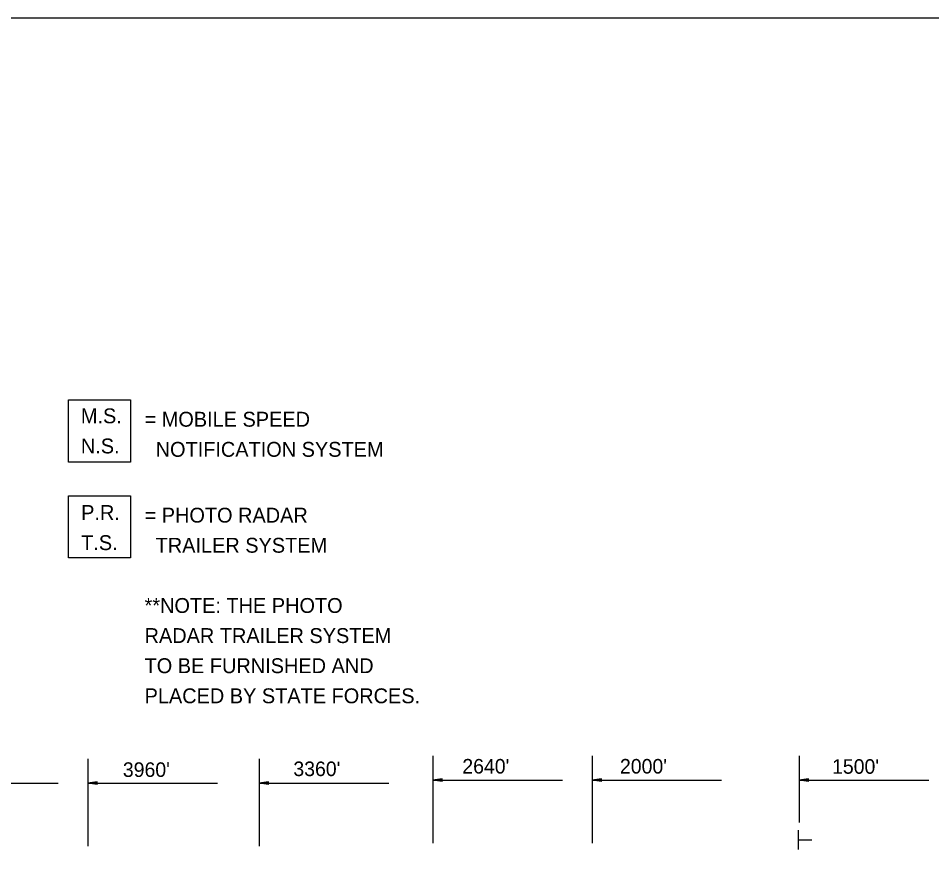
# Model space of a CAD drawing. Extents: x -100 to 745, y -1581 to -107.
# Drawn here: x 610.84 to 647.64, y -300.37 to -266.79 of the extents above; entities that cross this region are included whole.
import ezdxf

# ---------------------------------------------------------------- set-up
doc = ezdxf.new("R2010")
doc.units = 0
doc.layers.add('Default', color=7, linetype='Continuous')
doc.layers.add('R_Proposed Road', color=7, linetype='Continuous')

msp = doc.modelspace()

# ---------------------------------------------------------------- linework, layer by layer
at = {"layer": 'Default'}
for p, q in [((613.642, -296.624), (613.642, -300.145)), ((620.542, -296.624), (620.542, -300.145)), ((627.539, -296.504), (627.539, -300.025)), ((633.955, -296.504), (633.955, -300.025)), ((642.307, -296.504), (642.307, -299.189)), ((607.226, -297.603), (612.445, -297.603)), ((614.017, -297.547), (613.642, -297.603)), ((613.642, -297.603), (618.861, -297.603)), ((614.017, -297.659), (613.642, -297.603)), ((614.017, -297.556), (613.704, -297.603)), ((614.017, -297.65), (613.704, -297.603)), ((614.017, -297.566), (613.769, -297.603)), ((614.017, -297.64), (613.769, -297.603)), ((614.017, -297.575), (613.831, -297.603)), ((614.017, -297.631), (613.831, -297.603)), ((614.017, -297.584), (613.895, -297.603)), ((614.017, -297.621), (613.895, -297.603)), ((614.017, -297.594), (613.957, -297.603)), ((614.017, -297.612), (613.957, -297.603)), ((614.017, -297.659), (614.017, -297.547)), ((620.917, -297.547), (620.542, -297.603)), ((620.542, -297.603), (625.761, -297.603)), ((620.917, -297.659), (620.542, -297.603)), ((620.917, -297.556), (620.605, -297.603)), ((620.917, -297.65), (620.605, -297.603)), ((620.917, -297.566), (620.669, -297.603)), ((620.917, -297.64), (620.669, -297.603)), ((620.917, -297.575), (620.732, -297.603)), ((620.917, -297.631), (620.732, -297.603)), ((620.917, -297.584), (620.795, -297.603)), ((620.917, -297.621), (620.795, -297.603)), ((620.917, -297.594), (620.858, -297.603)), ((620.917, -297.612), (620.858, -297.603)), ((620.917, -297.659), (620.917, -297.547)), ((627.914, -297.427), (627.539, -297.483)), ((627.539, -297.483), (632.758, -297.483)), ((627.914, -297.539), (627.539, -297.483)), ((627.914, -297.436), (627.601, -297.483)), ((627.914, -297.53), (627.601, -297.483)), ((627.914, -297.446), (627.666, -297.483)), ((627.914, -297.52), (627.666, -297.483)), ((627.914, -297.455), (627.728, -297.483)), ((627.914, -297.511), (627.728, -297.483)), ((627.914, -297.465), (627.792, -297.483)), ((627.914, -297.501), (627.792, -297.483)), ((627.914, -297.474), (627.854, -297.483)), ((627.914, -297.492), (627.854, -297.483)), ((627.914, -297.539), (627.914, -297.427)), ((634.33, -297.427), (633.955, -297.483)), ((633.955, -297.483), (639.174, -297.483)), ((634.33, -297.539), (633.955, -297.483)), ((634.33, -297.436), (634.017, -297.483)), ((634.33, -297.53), (634.017, -297.483)), ((634.33, -297.446), (634.082, -297.483)), ((634.33, -297.52), (634.082, -297.483)), ((634.33, -297.455), (634.144, -297.483)), ((634.33, -297.511), (634.144, -297.483)), ((634.33, -297.465), (634.208, -297.483)), ((634.33, -297.501), (634.208, -297.483)), ((634.33, -297.474), (634.271, -297.483)), ((634.33, -297.492), (634.271, -297.483)), ((634.33, -297.539), (634.33, -297.427)), ((642.682, -297.427), (642.307, -297.483)), ((642.307, -297.483), (647.526, -297.483)), ((642.682, -297.539), (642.307, -297.483)), ((642.682, -297.436), (642.37, -297.483)), ((642.682, -297.53), (642.37, -297.483)), ((642.682, -297.446), (642.434, -297.483)), ((642.682, -297.52), (642.434, -297.483)), ((642.682, -297.455), (642.497, -297.483)), ((642.682, -297.511), (642.497, -297.483)), ((642.682, -297.465), (642.56, -297.483)), ((642.682, -297.501), (642.56, -297.483)), ((642.682, -297.474), (642.623, -297.483)), ((642.682, -297.492), (642.623, -297.483)), ((642.682, -297.539), (642.682, -297.427)), ((642.271, -300.275), (642.271, -299.493)), ((642.282, -299.886), (642.816, -299.886))]:
    msp.add_line(p, q, dxfattribs=at)
for points in [[(612.86, -284.665), (612.86, -282.165), (615.36, -282.165), (615.36, -284.665)], [(612.86, -288.53), (612.86, -286.03), (615.36, -286.03), (615.36, -288.53)]]:
    msp.add_lwpolyline(points, close=True, dxfattribs=at)
at = {"layer": 'R_Proposed Road'}
msp.add_lwpolyline([(574.769, -266.786), (574.769, -376.786), (744.769, -376.786), (744.769, -266.786)], close=True, dxfattribs=at)

# ---------------------------------------------------------------- texts
at = {"layer": 'Default'}
for s, height, p in [('M.S.', 0.6, (613.358, -283.104)), ('= MOBILE SPEED', 0.6, (615.925, -283.241)), ('N.S.', 0.6, (613.358, -284.317)), ('  NOTIFICATION SYSTEM', 0.6, (615.925, -284.454)), ('P.R.', 0.6, (613.369, -287)), ('= PHOTO RADAR', 0.6, (615.925, -287.106)), ('T.S.', 0.6, (613.369, -288.213)), ('  TRAILER SYSTEM', 0.6, (615.925, -288.319)), ('**NOTE: THE PHOTO', 0.6, (615.925, -290.745)), ('RADAR TRAILER SYSTEM', 0.6, (615.925, -291.958)), ('TO BE FURNISHED AND', 0.6, (615.925, -293.171)), ('PLACED BY STATE FORCES.', 0.6, (615.925, -294.384)), ("2640'", 0.5862, (628.728, -297.215)), ("2000'", 0.5862, (635.08, -297.215)), ("1500'", 0.5862, (643.626, -297.224)), ("3960'", 0.5862, (615.05, -297.351)), ("3360'", 0.5862, (621.92, -297.318))]:
    msp.add_text(s, height=height, dxfattribs=at).set_placement(p)

doc.saveas('drawing.dxf')
